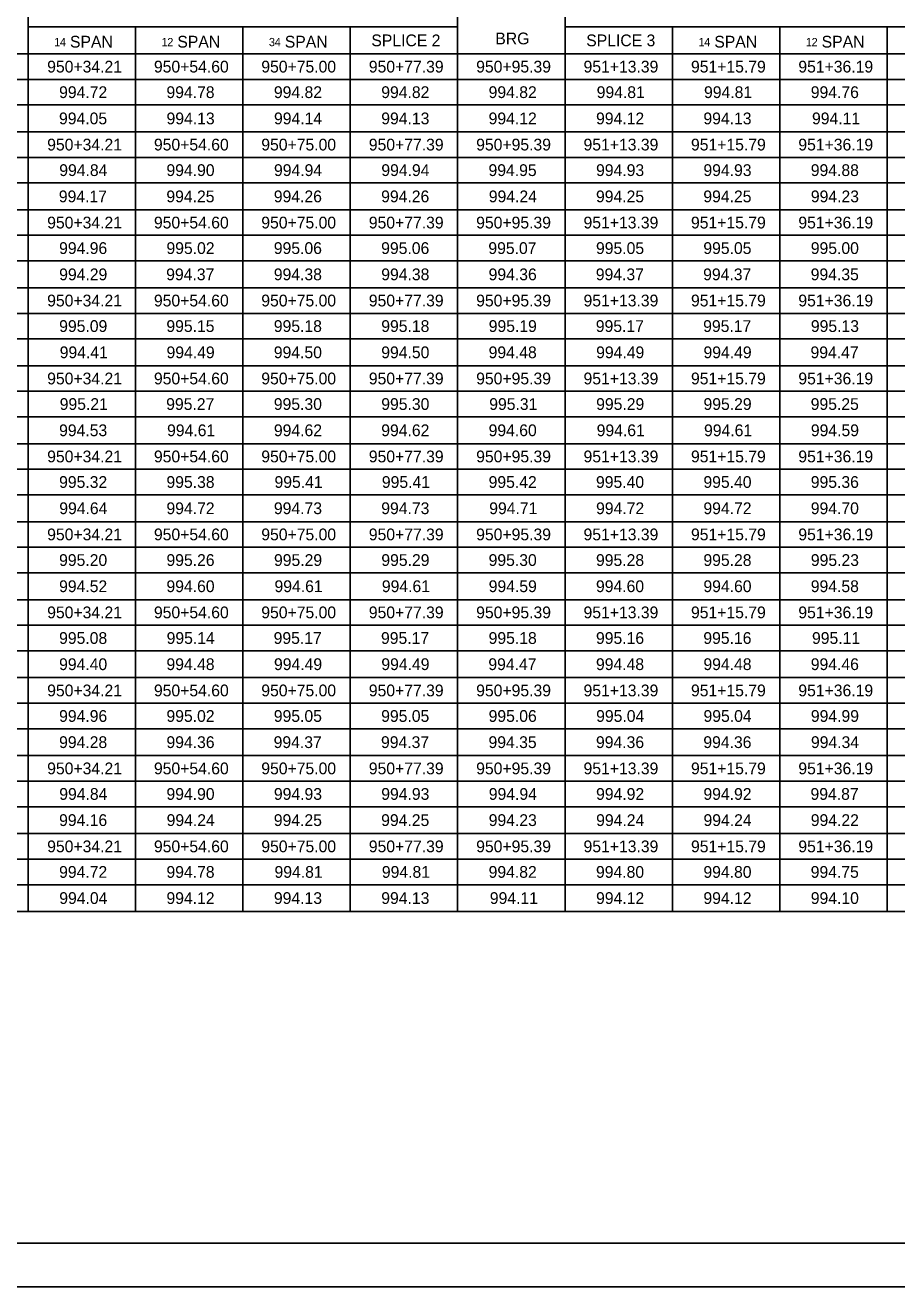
# Model space of a CAD drawing. Extents: x 0 to 34, y 0 to 22.
# Drawn here: x 13.14 to 23.16, y 0 to 14.51 of the extents above; entities that cross this region are included whole.
import ezdxf

# ---------------------------------------------------------------- set-up
doc = ezdxf.new("R2010")
doc.units = 0
for name, color, linetype in [('GT_Project_Soil_Boring', 7, 'Continuous'), ('SH_Cut_Line', 7, 'Continuous'), ('SH_Data', 7, 'Continuous')]:
    doc.layers.add(name, color=color, linetype=linetype)

msp = doc.modelspace()

# ---------------------------------------------------------------- linework, layer by layer
at = {"layer": 'GT_Project_Soil_Boring'}
for p, q in [((13.171, 14.788), (13.171, 4.317)), ((18.112, 14.788), (18.112, 4.317)), ((19.348, 14.788), (19.348, 4.317)), ((13.171, 14.494), (18.112, 14.494)), ((14.406, 14.494), (14.406, 4.317)), ((15.642, 14.494), (15.642, 4.317)), ((16.877, 14.494), (16.877, 4.317)), ((19.348, 14.494), (24.289, 14.494)), ((20.583, 14.494), (20.583, 4.317)), ((21.818, 14.494), (21.818, 4.317)), ((23.053, 14.494), (23.053, 4.317)), ((1.818, 14.185), (31.701, 14.185)), ((3.803, 13.891), (31.701, 13.891)), ((3.803, 13.597), (31.701, 13.597)), ((1.818, 13.288), (31.701, 13.288)), ((3.803, 12.994), (31.701, 12.994)), ((3.803, 12.699), (31.701, 12.699)), ((1.818, 12.391), (31.701, 12.391)), ((3.803, 12.097), (31.701, 12.097)), ((3.803, 11.802), (31.701, 11.802)), ((1.818, 11.494), (31.701, 11.494)), ((3.803, 11.199), (31.701, 11.199)), ((3.803, 10.905), (31.701, 10.905)), ((1.818, 10.596), (31.701, 10.596)), ((3.803, 10.302), (31.701, 10.302)), ((3.803, 10.008), (31.701, 10.008)), ((1.818, 9.699), (31.701, 9.699)), ((3.803, 9.405), (31.701, 9.405)), ((3.803, 9.111), (31.701, 9.111)), ((1.818, 8.802), (31.701, 8.802)), ((3.803, 8.508), (31.701, 8.508)), ((3.803, 8.214), (31.701, 8.214)), ((1.818, 7.905), (31.701, 7.905)), ((3.803, 7.611), (31.701, 7.611)), ((3.803, 7.317), (31.701, 7.317)), ((1.818, 7.008), (31.701, 7.008)), ((3.803, 6.714), (31.701, 6.714)), ((3.803, 6.42), (31.701, 6.42)), ((1.818, 6.111), (31.701, 6.111)), ((3.803, 5.817), (31.701, 5.817)), ((3.803, 5.523), (31.701, 5.523)), ((1.818, 5.214), (31.701, 5.214)), ((3.803, 4.92), (31.701, 4.92)), ((3.803, 4.626), (31.701, 4.626)), ((1.818, 4.317), (31.701, 4.317))]:
    msp.add_line(p, q, dxfattribs=at)
at = {"layer": 'SH_Cut_Line'}
msp.add_lwpolyline([(0, 0), (34, 0), (34, 22), (0, 22)], close=True, dxfattribs=at)
at = {"layer": 'SH_Data'}
msp.add_lwpolyline([(1.5, 21.5), (33.5, 21.5), (33.5, 0.5), (1.5, 0.5)], close=True, dxfattribs=at)

# ---------------------------------------------------------------- texts
at = {"layer": 'GT_Project_Soil_Boring'}
for s, height, p in [(' SPAN', 0.1353, (13.603, 14.257)), ('2', 0.0947, (14.772, 14.273)), (' SPAN', 0.1353, (14.838, 14.257)), ('3', 0.0947, (15.941, 14.273)), (' SPAN', 0.1353, (16.074, 14.257)), ('SPLICE 2', 0.1353, (17.12, 14.272)), ('BRG', 0.1353, (18.546, 14.294)), ('SPLICE 3', 0.1353, (19.592, 14.272)), (' SPAN', 0.1353, (21.015, 14.257)), ('2', 0.0947, (22.184, 14.273)), (' SPAN', 0.1353, (22.25, 14.257)), ('1', 0.0947, (13.471, 14.273)), ('4', 0.0947, (13.537, 14.273)), ('1', 0.0947, (14.706, 14.273)), ('4', 0.0947, (16.008, 14.273)), ('1', 0.0947, (20.883, 14.273)), ('4', 0.0947, (20.949, 14.273)), ('1', 0.0947, (22.118, 14.273)), ('950+34.21', 0.1353, (13.391, 13.97)), ('950+54.60', 0.1353, (14.619, 13.97)), ('950+75.00', 0.1353, (15.854, 13.97)), ('950+77.39', 0.1353, (17.091, 13.97)), ('950+95.39', 0.1353, (18.326, 13.97)), ('951+13.39', 0.1353, (19.561, 13.97)), ('951+15.79', 0.1353, (20.797, 13.97)), ('951+36.19', 0.1353, (22.032, 13.97)), ('994.72', 0.1353, (13.528, 13.676)), ('994.78', 0.1353, (14.763, 13.676)), ('994.82', 0.1353, (15.999, 13.676)), ('994.82', 0.1353, (17.234, 13.676)), ('994.82', 0.1353, (18.469, 13.676)), ('994.81', 0.1353, (19.712, 13.676)), ('994.81', 0.1353, (20.947, 13.676)), ('994.76', 0.1353, (22.175, 13.676)), ('994.05', 0.1353, (13.527, 13.374)), ('994.13', 0.1353, (14.764, 13.374)), ('994.14', 0.1353, (16, 13.374)), ('994.13', 0.1353, (17.234, 13.374)), ('994.12', 0.1353, (18.469, 13.374)), ('994.12', 0.1353, (19.705, 13.374)), ('994.13', 0.1353, (20.94, 13.374)), ('994.11', 0.1353, (22.189, 13.374)), ('950+34.21', 0.1353, (13.391, 13.073)), ('950+54.60', 0.1353, (14.619, 13.073)), ('950+75.00', 0.1353, (15.854, 13.073)), ('950+77.39', 0.1353, (17.091, 13.073)), ('950+95.39', 0.1353, (18.326, 13.073)), ('951+13.39', 0.1353, (19.561, 13.073)), ('951+15.79', 0.1353, (20.797, 13.073)), ('951+36.19', 0.1353, (22.032, 13.073)), ('994.84', 0.1353, (13.53, 12.779)), ('994.90', 0.1353, (14.763, 12.779)), ('994.94', 0.1353, (16, 12.779)), ('994.94', 0.1353, (17.235, 12.779)), ('994.95', 0.1353, (18.468, 12.779)), ('994.93', 0.1353, (19.705, 12.779)), ('994.93', 0.1353, (20.94, 12.779)), ('994.88', 0.1353, (22.175, 12.779)), ('994.17', 0.1353, (13.525, 12.477)), ('994.25', 0.1353, (14.762, 12.477)), ('994.26', 0.1353, (15.998, 12.477)), ('994.26', 0.1353, (17.233, 12.477)), ('994.24', 0.1353, (18.471, 12.477)), ('994.25', 0.1353, (19.704, 12.477)), ('994.25', 0.1353, (20.939, 12.477)), ('994.23', 0.1353, (22.176, 12.477)), ('950+34.21', 0.1353, (13.391, 12.176)), ('950+54.60', 0.1353, (14.619, 12.176)), ('950+75.00', 0.1353, (15.854, 12.176)), ('950+77.39', 0.1353, (17.091, 12.176)), ('950+95.39', 0.1353, (18.326, 12.176)), ('951+13.39', 0.1353, (19.561, 12.176)), ('951+15.79', 0.1353, (20.797, 12.176)), ('951+36.19', 0.1353, (22.032, 12.176)), ('994.96', 0.1353, (13.528, 11.882)), ('995.02', 0.1353, (14.763, 11.882)), ('995.06', 0.1353, (15.998, 11.882)), ('995.06', 0.1353, (17.233, 11.882)), ('995.07', 0.1353, (18.466, 11.882)), ('995.05', 0.1353, (19.704, 11.882)), ('995.05', 0.1353, (20.939, 11.882)), ('995.00', 0.1353, (22.175, 11.882)), ('994.29', 0.1353, (13.529, 11.58)), ('994.37', 0.1353, (14.76, 11.58)), ('994.38', 0.1353, (15.998, 11.58)), ('994.38', 0.1353, (17.234, 11.58)), ('994.36', 0.1353, (18.469, 11.58)), ('994.37', 0.1353, (19.702, 11.58)), ('994.37', 0.1353, (20.937, 11.58)), ('994.35', 0.1353, (22.174, 11.58)), ('950+34.21', 0.1353, (13.391, 11.279)), ('950+54.60', 0.1353, (14.619, 11.279)), ('950+75.00', 0.1353, (15.854, 11.279)), ('950+77.39', 0.1353, (17.091, 11.279)), ('950+95.39', 0.1353, (18.326, 11.279)), ('951+13.39', 0.1353, (19.561, 11.279)), ('951+15.79', 0.1353, (20.797, 11.279)), ('951+36.19', 0.1353, (22.032, 11.279)), ('995.09', 0.1353, (13.529, 10.985)), ('995.15', 0.1353, (14.762, 10.985)), ('995.18', 0.1353, (15.998, 10.985)), ('995.18', 0.1353, (17.234, 10.985)), ('995.19', 0.1353, (18.47, 10.985)), ('995.17', 0.1353, (19.702, 10.985)), ('995.17', 0.1353, (20.937, 10.985)), ('995.13', 0.1353, (22.176, 10.985)), ('994.41', 0.1353, (13.535, 10.683)), ('994.49', 0.1353, (14.764, 10.683)), ('994.50', 0.1353, (15.998, 10.683)), ('994.50', 0.1353, (17.234, 10.683)), ('994.48', 0.1353, (18.469, 10.683)), ('994.49', 0.1353, (19.706, 10.683)), ('994.49', 0.1353, (20.941, 10.683)), ('994.47', 0.1353, (22.172, 10.683)), ('950+34.21', 0.1353, (13.391, 10.382)), ('950+54.60', 0.1353, (14.619, 10.382)), ('950+75.00', 0.1353, (15.854, 10.382)), ('950+77.39', 0.1353, (17.091, 10.382)), ('950+95.39', 0.1353, (18.326, 10.382)), ('951+13.39', 0.1353, (19.561, 10.382)), ('951+15.79', 0.1353, (20.797, 10.382)), ('951+36.19', 0.1353, (22.032, 10.382)), ('995.21', 0.1353, (13.535, 10.088)), ('995.27', 0.1353, (14.76, 10.088)), ('995.30', 0.1353, (15.998, 10.088)), ('995.30', 0.1353, (17.234, 10.088)), ('995.31', 0.1353, (18.476, 10.088)), ('995.29', 0.1353, (19.706, 10.088)), ('995.29', 0.1353, (20.941, 10.088)), ('995.25', 0.1353, (22.174, 10.088)), ('994.53', 0.1353, (13.528, 9.786)), ('994.61', 0.1353, (14.77, 9.786)), ('994.62', 0.1353, (15.999, 9.786)), ('994.62', 0.1353, (17.234, 9.786)), ('994.60', 0.1353, (18.469, 9.786)), ('994.61', 0.1353, (19.712, 9.786)), ('994.61', 0.1353, (20.947, 9.786)), ('994.59', 0.1353, (22.176, 9.786)), ('950+34.21', 0.1353, (13.391, 9.485)), ('950+54.60', 0.1353, (14.619, 9.485)), ('950+75.00', 0.1353, (15.854, 9.485)), ('950+77.39', 0.1353, (17.091, 9.485)), ('950+95.39', 0.1353, (18.326, 9.485)), ('951+13.39', 0.1353, (19.561, 9.485)), ('951+15.79', 0.1353, (20.797, 9.485)), ('951+36.19', 0.1353, (22.032, 9.485)), ('995.32', 0.1353, (13.528, 9.191)), ('995.38', 0.1353, (14.763, 9.191)), ('995.41', 0.1353, (16.006, 9.191)), ('995.41', 0.1353, (17.241, 9.191)), ('995.42', 0.1353, (18.469, 9.191)), ('995.40', 0.1353, (19.704, 9.191)), ('995.40', 0.1353, (20.94, 9.191)), ('995.36', 0.1353, (22.175, 9.191)), ('994.64', 0.1353, (13.53, 8.889)), ('994.72', 0.1353, (14.763, 8.889)), ('994.73', 0.1353, (15.999, 8.889)), ('994.73', 0.1353, (17.234, 8.889)), ('994.71', 0.1353, (18.476, 8.889)), ('994.72', 0.1353, (19.705, 8.889)), ('994.72', 0.1353, (20.94, 8.889)), ('994.70', 0.1353, (22.175, 8.889)), ('950+34.21', 0.1353, (13.391, 8.588)), ('950+54.60', 0.1353, (14.619, 8.588)), ('950+75.00', 0.1353, (15.854, 8.588)), ('950+77.39', 0.1353, (17.091, 8.588)), ('950+95.39', 0.1353, (18.326, 8.588)), ('951+13.39', 0.1353, (19.561, 8.588)), ('951+15.79', 0.1353, (20.797, 8.588)), ('951+36.19', 0.1353, (22.032, 8.588)), ('995.20', 0.1353, (13.528, 8.293)), ('995.26', 0.1353, (14.763, 8.293)), ('995.29', 0.1353, (16, 8.293)), ('995.29', 0.1353, (17.235, 8.293)), ('995.30', 0.1353, (18.469, 8.293)), ('995.28', 0.1353, (19.704, 8.293)), ('995.28', 0.1353, (20.94, 8.293)), ('995.23', 0.1353, (22.176, 8.293)), ('994.52', 0.1353, (13.528, 7.992)), ('994.60', 0.1353, (14.763, 7.992)), ('994.61', 0.1353, (16.006, 7.992)), ('994.61', 0.1353, (17.241, 7.992)), ('994.59', 0.1353, (18.47, 7.992)), ('994.60', 0.1353, (19.704, 7.992)), ('994.60', 0.1353, (20.94, 7.992)), ('994.58', 0.1353, (22.175, 7.992)), ('950+34.21', 0.1353, (13.391, 7.691)), ('950+54.60', 0.1353, (14.619, 7.691)), ('950+75.00', 0.1353, (15.854, 7.691)), ('950+77.39', 0.1353, (17.091, 7.691)), ('950+95.39', 0.1353, (18.326, 7.691)), ('951+13.39', 0.1353, (19.561, 7.691)), ('951+15.79', 0.1353, (20.797, 7.691)), ('951+36.19', 0.1353, (22.032, 7.691)), ('995.08', 0.1353, (13.528, 7.396)), ('995.14', 0.1353, (14.765, 7.396)), ('995.17', 0.1353, (15.996, 7.396)), ('995.17', 0.1353, (17.231, 7.396)), ('995.18', 0.1353, (18.469, 7.396)), ('995.16', 0.1353, (19.704, 7.396)), ('995.16', 0.1353, (20.939, 7.396)), ('995.11', 0.1353, (22.189, 7.396)), ('994.40', 0.1353, (13.528, 7.095)), ('994.48', 0.1353, (14.763, 7.095)), ('994.49', 0.1353, (16, 7.095)), ('994.49', 0.1353, (17.235, 7.095)), ('994.47', 0.1353, (18.466, 7.095)), ('994.48', 0.1353, (19.704, 7.095)), ('994.48', 0.1353, (20.94, 7.095)), ('994.46', 0.1353, (22.175, 7.095)), ('950+34.21', 0.1353, (13.391, 6.793)), ('950+54.60', 0.1353, (14.619, 6.793)), ('950+75.00', 0.1353, (15.854, 6.793)), ('950+77.39', 0.1353, (17.091, 6.793)), ('950+95.39', 0.1353, (18.326, 6.793)), ('951+13.39', 0.1353, (19.561, 6.793)), ('951+15.79', 0.1353, (20.797, 6.793)), ('951+36.19', 0.1353, (22.032, 6.793)), ('994.96', 0.1353, (13.528, 6.499)), ('995.02', 0.1353, (14.763, 6.499)), ('995.05', 0.1353, (15.998, 6.499)), ('995.05', 0.1353, (17.233, 6.499)), ('995.06', 0.1353, (18.469, 6.499)), ('995.04', 0.1353, (19.706, 6.499)), ('995.04', 0.1353, (20.941, 6.499)), ('994.99', 0.1353, (22.176, 6.499)), ('994.28', 0.1353, (13.528, 6.198)), ('994.36', 0.1353, (14.763, 6.198)), ('994.37', 0.1353, (15.996, 6.198)), ('994.37', 0.1353, (17.231, 6.198)), ('994.35', 0.1353, (18.468, 6.198)), ('994.36', 0.1353, (19.704, 6.198)), ('994.36', 0.1353, (20.939, 6.198)), ('994.34', 0.1353, (22.177, 6.198)), ('950+34.21', 0.1353, (13.391, 5.896)), ('950+54.60', 0.1353, (14.619, 5.896)), ('950+75.00', 0.1353, (15.854, 5.896)), ('950+77.39', 0.1353, (17.091, 5.896)), ('950+95.39', 0.1353, (18.326, 5.896)), ('951+13.39', 0.1353, (19.561, 5.896)), ('951+15.79', 0.1353, (20.797, 5.896)), ('951+36.19', 0.1353, (22.032, 5.896)), ('994.84', 0.1353, (13.53, 5.602)), ('994.90', 0.1353, (14.763, 5.602)), ('994.93', 0.1353, (15.999, 5.602)), ('994.93', 0.1353, (17.234, 5.602)), ('994.94', 0.1353, (18.471, 5.602)), ('994.92', 0.1353, (19.705, 5.602)), ('994.92', 0.1353, (20.94, 5.602)), ('994.87', 0.1353, (22.172, 5.602)), ('994.16', 0.1353, (13.528, 5.301)), ('994.24', 0.1353, (14.765, 5.301)), ('994.25', 0.1353, (15.998, 5.301)), ('994.25', 0.1353, (17.233, 5.301)), ('994.23', 0.1353, (18.47, 5.301)), ('994.24', 0.1353, (19.706, 5.301)), ('994.24', 0.1353, (20.941, 5.301)), ('994.22', 0.1353, (22.175, 5.301)), ('950+34.21', 0.1353, (13.391, 4.999)), ('950+54.60', 0.1353, (14.619, 4.999)), ('950+75.00', 0.1353, (15.854, 4.999)), ('950+77.39', 0.1353, (17.091, 4.999)), ('950+95.39', 0.1353, (18.326, 4.999)), ('951+13.39', 0.1353, (19.561, 4.999)), ('951+15.79', 0.1353, (20.797, 4.999)), ('951+36.19', 0.1353, (22.032, 4.999)), ('994.72', 0.1353, (13.528, 4.705)), ('994.78', 0.1353, (14.763, 4.705)), ('994.81', 0.1353, (16.006, 4.705)), ('994.81', 0.1353, (17.241, 4.705)), ('994.82', 0.1353, (18.469, 4.705)), ('994.80', 0.1353, (19.704, 4.705)), ('994.80', 0.1353, (20.94, 4.705)), ('994.75', 0.1353, (22.174, 4.705)), ('994.04', 0.1353, (13.53, 4.404)), ('994.12', 0.1353, (14.763, 4.404)), ('994.13', 0.1353, (15.999, 4.404)), ('994.13', 0.1353, (17.234, 4.404)), ('994.11', 0.1353, (18.483, 4.404)), ('994.12', 0.1353, (19.705, 4.404)), ('994.12', 0.1353, (20.94, 4.404)), ('994.10', 0.1353, (22.175, 4.404))]:
    msp.add_text(s, height=height, dxfattribs=at).set_placement(p)

doc.saveas('drawing.dxf')
